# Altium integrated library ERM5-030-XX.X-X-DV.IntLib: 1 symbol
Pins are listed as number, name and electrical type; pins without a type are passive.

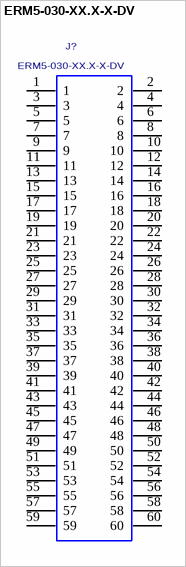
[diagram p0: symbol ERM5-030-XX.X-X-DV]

## ERM5-030-XX.X-X-DV
designator J?
Terminal Assembly, Double Row Vertical, Surface Mount, 0.5mm Pitch, 60 Pins.; MANUFACTURER: SAMTEC
footprint ERM5-030-XX.X-X-DV
pins: 1, 2, 3, 4, 5, 6, 7, 8, 9, 10, 11, 12, 13, 14, 15, 16, 17, 18, 19, 20, 21, 22, 23, 24, 25, 26, 27, 28, 29, 30, 31, 32, 33, 34, 35, 36, 37, 38, 39, 40, 41, 42, 43, 44, 45, 46, 47, 48, 49, 50, 51, 52, 53, 54, 55, 56, 57, 58, 59, 60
